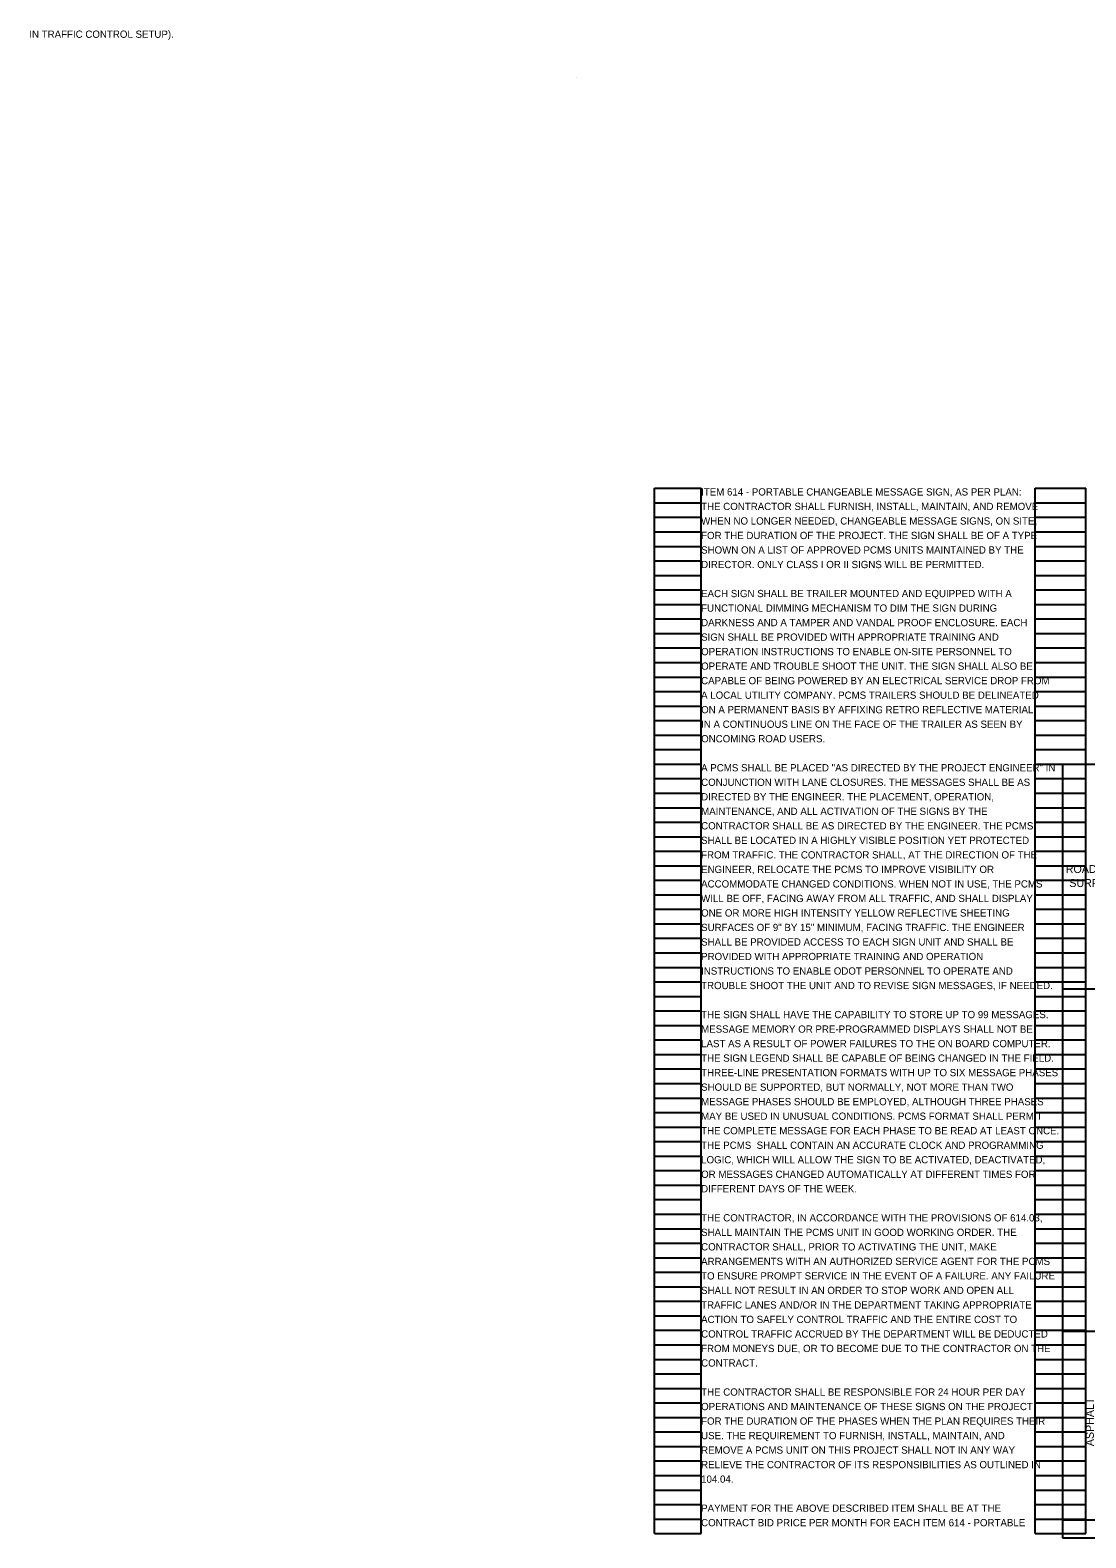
# Model space of a CAD drawing. Extents: x 0 to 37668, y -5 to 18949.
# Drawn here: x 37625.86 to 37646.22, y 18868.37 to 18897.45 of the extents above; entities that cross this region are included whole.
import ezdxf

# ---------------------------------------------------------------- set-up
doc = ezdxf.new("R2010")
doc.units = 0
doc.layers.add('SH_Data', color=7, linetype='Continuous')
doc.layers.add('SH_Text', color=7, linetype='Continuous')

msp = doc.modelspace()

# ---------------------------------------------------------------- linework, layer by layer
at = {"layer": 'SH_Data'}
for p, q in [((37636.401, 18896.542), (37636.401, 18896.542)), ((37637.901, 18868.45), (37637.901, 18888.61)), ((37637.901, 18888.61), (37638.801, 18888.61)), ((37638.801, 18868.45), (37638.801, 18888.61)), ((37645.241, 18868.45), (37645.241, 18888.61)), ((37645.241, 18888.61), (37646.221, 18888.61)), ((37646.221, 18868.45), (37646.221, 18888.61)), ((37637.901, 18888.33), (37638.801, 18888.33)), ((37645.241, 18888.33), (37646.221, 18888.33)), ((37637.901, 18888.05), (37638.801, 18888.05)), ((37645.241, 18888.05), (37646.221, 18888.05)), ((37637.901, 18887.77), (37638.801, 18887.77)), ((37645.241, 18887.77), (37646.221, 18887.77)), ((37637.901, 18887.49), (37638.801, 18887.49)), ((37645.241, 18887.49), (37646.221, 18887.49)), ((37637.901, 18887.21), (37638.801, 18887.21)), ((37637.901, 18886.93), (37638.801, 18886.93)), ((37645.241, 18887.21), (37646.221, 18887.21)), ((37645.241, 18886.93), (37646.221, 18886.93)), ((37637.901, 18886.65), (37638.801, 18886.65)), ((37645.241, 18886.65), (37646.221, 18886.65)), ((37637.901, 18886.37), (37638.801, 18886.37)), ((37645.241, 18886.37), (37646.221, 18886.37)), ((37637.901, 18886.09), (37638.801, 18886.09)), ((37645.241, 18886.09), (37646.221, 18886.09)), ((37637.901, 18885.81), (37638.801, 18885.81)), ((37645.241, 18885.81), (37646.221, 18885.81)), ((37637.901, 18885.53), (37638.801, 18885.53)), ((37645.241, 18885.53), (37646.221, 18885.53)), ((37637.901, 18885.25), (37638.801, 18885.25)), ((37645.241, 18885.25), (37646.221, 18885.25)), ((37637.901, 18884.97), (37638.801, 18884.97)), ((37645.241, 18884.97), (37646.221, 18884.97)), ((37637.901, 18884.69), (37638.801, 18884.69)), ((37645.241, 18884.69), (37646.221, 18884.69)), ((37637.901, 18884.41), (37638.801, 18884.41)), ((37645.241, 18884.41), (37646.221, 18884.41)), ((37637.901, 18884.13), (37638.801, 18884.13)), ((37645.241, 18884.13), (37646.221, 18884.13)), ((37637.901, 18883.85), (37638.801, 18883.85)), ((37645.241, 18883.85), (37646.221, 18883.85)), ((37637.901, 18883.57), (37638.801, 18883.57)), ((37645.241, 18883.57), (37646.221, 18883.57)), ((37637.901, 18883.29), (37638.801, 18883.29)), ((37645.241, 18883.29), (37646.221, 18883.29)), ((37637.901, 18883.01), (37638.801, 18883.01)), ((37645.241, 18883.01), (37646.221, 18883.01)), ((37637.901, 18882.73), (37638.801, 18882.73)), ((37645.241, 18882.73), (37646.221, 18882.73)), ((37637.901, 18882.45), (37638.801, 18882.45)), ((37645.241, 18882.45), (37646.221, 18882.45)), ((37637.901, 18882.17), (37638.801, 18882.17)), ((37645.241, 18882.17), (37646.221, 18882.17)), ((37637.901, 18881.89), (37638.801, 18881.89)), ((37645.241, 18881.89), (37646.221, 18881.89)), ((37637.901, 18881.61), (37638.801, 18881.61)), ((37645.241, 18881.61), (37646.221, 18881.61)), ((37637.901, 18881.33), (37638.801, 18881.33)), ((37645.241, 18881.33), (37646.221, 18881.33)), ((37637.901, 18881.05), (37638.801, 18881.05)), ((37645.241, 18881.05), (37646.221, 18881.05)), ((37637.901, 18880.77), (37638.801, 18880.77)), ((37645.241, 18880.77), (37646.221, 18880.77)), ((37637.901, 18880.49), (37638.801, 18880.49)), ((37645.241, 18880.49), (37646.221, 18880.49)), ((37637.901, 18880.21), (37638.801, 18880.21)), ((37645.241, 18880.21), (37646.221, 18880.21)), ((37637.901, 18879.93), (37638.801, 18879.93)), ((37645.241, 18879.93), (37646.221, 18879.93)), ((37637.901, 18879.65), (37638.801, 18879.65)), ((37637.901, 18879.37), (37638.801, 18879.37)), ((37645.241, 18879.65), (37646.221, 18879.65)), ((37645.241, 18879.37), (37646.221, 18879.37)), ((37637.901, 18879.09), (37638.801, 18879.09)), ((37645.241, 18879.09), (37646.221, 18879.09)), ((37637.901, 18878.81), (37638.801, 18878.81)), ((37645.241, 18878.81), (37646.221, 18878.81)), ((37637.901, 18878.53), (37638.801, 18878.53)), ((37645.241, 18878.53), (37646.221, 18878.53)), ((37637.901, 18878.25), (37638.801, 18878.25)), ((37645.241, 18878.25), (37646.221, 18878.25)), ((37637.901, 18877.97), (37638.801, 18877.97)), ((37645.241, 18877.97), (37646.221, 18877.97)), ((37637.901, 18877.69), (37638.801, 18877.69)), ((37645.241, 18877.69), (37646.221, 18877.69)), ((37637.901, 18877.41), (37638.801, 18877.41)), ((37645.241, 18877.41), (37646.221, 18877.41)), ((37637.901, 18877.13), (37638.801, 18877.13)), ((37645.241, 18877.13), (37646.221, 18877.13)), ((37637.901, 18876.85), (37638.801, 18876.85)), ((37645.241, 18876.85), (37646.221, 18876.85)), ((37637.901, 18876.57), (37638.801, 18876.57)), ((37645.241, 18876.57), (37646.221, 18876.57)), ((37637.901, 18876.29), (37638.801, 18876.29)), ((37645.241, 18876.29), (37646.221, 18876.29)), ((37637.901, 18876.01), (37638.801, 18876.01)), ((37645.241, 18876.01), (37646.221, 18876.01)), ((37637.901, 18875.73), (37638.801, 18875.73)), ((37645.241, 18875.73), (37646.221, 18875.73)), ((37637.901, 18875.45), (37638.801, 18875.45)), ((37645.241, 18875.45), (37646.221, 18875.45)), ((37637.901, 18875.17), (37638.801, 18875.17)), ((37645.241, 18875.17), (37646.221, 18875.17)), ((37637.901, 18874.89), (37638.801, 18874.89)), ((37645.241, 18874.89), (37646.221, 18874.89)), ((37637.901, 18874.61), (37638.801, 18874.61)), ((37645.241, 18874.61), (37646.221, 18874.61)), ((37637.901, 18874.33), (37638.801, 18874.33)), ((37645.241, 18874.33), (37646.221, 18874.33)), ((37637.901, 18874.05), (37638.801, 18874.05)), ((37645.241, 18874.05), (37646.221, 18874.05)), ((37637.901, 18873.77), (37638.801, 18873.77)), ((37645.241, 18873.77), (37646.221, 18873.77)), ((37637.901, 18873.49), (37638.801, 18873.49)), ((37645.241, 18873.49), (37646.221, 18873.49)), ((37637.901, 18873.21), (37638.801, 18873.21)), ((37645.241, 18873.21), (37646.221, 18873.21)), ((37637.901, 18872.93), (37638.801, 18872.93)), ((37645.241, 18872.93), (37646.221, 18872.93)), ((37637.901, 18872.65), (37638.801, 18872.65)), ((37645.241, 18872.65), (37646.221, 18872.65)), ((37637.901, 18872.37), (37638.801, 18872.37)), ((37645.241, 18872.37), (37646.221, 18872.37)), ((37637.901, 18872.09), (37638.801, 18872.09)), ((37637.901, 18871.81), (37638.801, 18871.81)), ((37645.241, 18872.09), (37646.221, 18872.09)), ((37645.241, 18871.81), (37646.221, 18871.81)), ((37637.901, 18871.53), (37638.801, 18871.53)), ((37645.241, 18871.53), (37646.221, 18871.53)), ((37637.901, 18871.25), (37638.801, 18871.25)), ((37645.241, 18871.25), (37646.221, 18871.25)), ((37637.901, 18870.97), (37638.801, 18870.97)), ((37645.241, 18870.97), (37646.221, 18870.97)), ((37637.901, 18870.69), (37638.801, 18870.69)), ((37645.241, 18870.69), (37646.221, 18870.69)), ((37637.901, 18870.41), (37638.801, 18870.41)), ((37645.241, 18870.41), (37646.221, 18870.41)), ((37637.901, 18870.13), (37638.801, 18870.13)), ((37645.241, 18870.13), (37646.221, 18870.13)), ((37637.901, 18869.85), (37638.801, 18869.85)), ((37645.241, 18869.85), (37646.221, 18869.85)), ((37637.901, 18869.57), (37638.801, 18869.57)), ((37645.241, 18869.57), (37646.221, 18869.57)), ((37637.901, 18869.29), (37638.801, 18869.29)), ((37645.241, 18869.29), (37646.221, 18869.29)), ((37637.901, 18869.01), (37638.801, 18869.01)), ((37645.241, 18869.01), (37646.221, 18869.01)), ((37637.901, 18868.73), (37638.801, 18868.73)), ((37645.241, 18868.73), (37646.221, 18868.73)), ((37637.901, 18868.45), (37638.801, 18868.45)), ((37645.241, 18868.45), (37646.221, 18868.45))]:
    msp.add_line(p, q, dxfattribs=at)
at = {"layer": 'SH_Text'}
for p, q in [((37645.771, 18883.29), (37658.947, 18883.29)), ((37645.771, 18883.29), (37645.771, 18868.367)), ((37645.771, 18878.958), (37658.947, 18878.958)), ((37645.771, 18872.353), (37658.947, 18872.353)), ((37645.771, 18868.713), (37658.947, 18868.713)), ((37645.771, 18868.367), (37658.947, 18868.367))]:
    msp.add_line(p, q, dxfattribs=at)

# ---------------------------------------------------------------- texts
for s, height, p in [('IN TRAFFIC CONTROL SETUP).', 0.14, (37625.844, 18897.298)), ('ITEM 614 - PORTABLE CHANGEABLE MESSAGE SIGN, AS PER PLAN:', 0.14, (37638.801, 18888.47)), ('THE CONTRACTOR SHALL FURNISH, INSTALL, MAINTAIN, AND REMOVE ', 0.14, (37638.801, 18888.19)), ('WHEN NO LONGER NEEDED, CHANGEABLE MESSAGE SIGNS, ON SITE, ', 0.14, (37638.801, 18887.91)), ('FOR THE DURATION OF THE PROJECT. THE SIGN SHALL BE OF A TYPE ', 0.14, (37638.801, 18887.63)), ('SHOWN ON A LIST OF APPROVED PCMS UNITS MAINTAINED BY THE ', 0.14, (37638.801, 18887.35)), ('DIRECTOR. ONLY CLASS I OR II SIGNS WILL BE PERMITTED.', 0.14, (37638.801, 18887.07)), ('EACH SIGN SHALL BE TRAILER MOUNTED AND EQUIPPED WITH A ', 0.14, (37638.801, 18886.51)), ('FUNCTIONAL DIMMING MECHANISM TO DIM THE SIGN DURING ', 0.14, (37638.801, 18886.23)), ('DARKNESS AND A TAMPER AND VANDAL PROOF ENCLOSURE. EACH ', 0.14, (37638.801, 18885.95)), ('SIGN SHALL BE PROVIDED WITH APPROPRIATE TRAINING AND ', 0.14, (37638.801, 18885.67)), ('OPERATION INSTRUCTIONS TO ENABLE ON-SITE PERSONNEL TO ', 0.14, (37638.801, 18885.39)), ('OPERATE AND TROUBLE SHOOT THE UNIT. THE SIGN SHALL ALSO BE ', 0.14, (37638.801, 18885.11)), ('CAPABLE OF BEING POWERED BY AN ELECTRICAL SERVICE DROP FROM ', 0.14, (37638.801, 18884.83)), ('A LOCAL UTILITY COMPANY. PCMS TRAILERS SHOULD BE DELINEATED ', 0.14, (37638.801, 18884.55)), ('ON A PERMANENT BASIS BY AFFIXING RETRO REFLECTIVE MATERIAL, ', 0.14, (37638.801, 18884.27)), ('IN A CONTINUOUS LINE ON THE FACE OF THE TRAILER AS SEEN BY ', 0.14, (37638.801, 18883.99)), ('ONCOMING ROAD USERS.', 0.14, (37638.801, 18883.71)), ('A PCMS SHALL BE PLACED "AS DIRECTED BY THE PROJECT ENGINEER" IN ', 0.14, (37638.801, 18883.15)), ('CONJUNCTION WITH LANE CLOSURES. THE MESSAGES SHALL BE AS ', 0.14, (37638.801, 18882.87)), ('DIRECTED BY THE ENGINEER. THE PLACEMENT, OPERATION, ', 0.14, (37638.801, 18882.59)), ('MAINTENANCE, AND ALL ACTIVATION OF THE SIGNS BY THE ', 0.14, (37638.801, 18882.31)), ('CONTRACTOR SHALL BE AS DIRECTED BY THE ENGINEER. THE PCMS ', 0.14, (37638.801, 18882.03)), ('SHALL BE LOCATED IN A HIGHLY VISIBLE POSITION YET PROTECTED ', 0.14, (37638.801, 18881.75)), ('FROM TRAFFIC. THE CONTRACTOR SHALL, AT THE DIRECTION OF THE ', 0.14, (37638.801, 18881.47)), ('ENGINEER, RELOCATE THE PCMS TO IMPROVE VISIBILITY OR ', 0.14, (37638.801, 18881.19)), ('ROADWAY ', 0.154, (37645.834, 18881.19)), ('ACCOMMODATE CHANGED CONDITIONS. WHEN NOT IN USE, THE PCMS ', 0.14, (37638.801, 18880.91)), ('SURFACE', 0.154, (37645.902, 18880.92)), ('WILL BE OFF, FACING AWAY FROM ALL TRAFFIC, AND SHALL DISPLAY ', 0.14, (37638.801, 18880.63)), ('ONE OR MORE HIGH INTENSITY YELLOW REFLECTIVE SHEETING ', 0.14, (37638.801, 18880.35)), ('SURFACES OF 9" BY 15" MINIMUM, FACING TRAFFIC. THE ENGINEER ', 0.14, (37638.801, 18880.07)), ('SHALL BE PROVIDED ACCESS TO EACH SIGN UNIT AND SHALL BE ', 0.14, (37638.801, 18879.79)), ('PROVIDED WITH APPROPRIATE TRAINING AND OPERATION ', 0.14, (37638.801, 18879.51)), ('INSTRUCTIONS TO ENABLE ODOT PERSONNEL TO OPERATE AND ', 0.14, (37638.801, 18879.23)), ('TROUBLE SHOOT THE UNIT AND TO REVISE SIGN MESSAGES, IF NEEDED.', 0.14, (37638.801, 18878.95)), ('THE SIGN SHALL HAVE THE CAPABILITY TO STORE UP TO 99 MESSAGES. ', 0.14, (37638.801, 18878.39)), ('MESSAGE MEMORY OR PRE-PROGRAMMED DISPLAYS SHALL NOT BE ', 0.14, (37638.801, 18878.11)), ('LAST AS A RESULT OF POWER FAILURES TO THE ON BOARD COMPUTER. ', 0.14, (37638.801, 18877.83)), ('THE SIGN LEGEND SHALL BE CAPABLE OF BEING CHANGED IN THE FIELD. ', 0.14, (37638.801, 18877.55)), ('THREE-LINE PRESENTATION FORMATS WITH UP TO SIX MESSAGE PHASES ', 0.14, (37638.801, 18877.27)), ('SHOULD BE SUPPORTED, BUT NORMALLY, NOT MORE THAN TWO ', 0.14, (37638.801, 18876.99)), ('MESSAGE PHASES SHOULD BE EMPLOYED, ALTHOUGH THREE PHASES ', 0.14, (37638.801, 18876.71)), ('MAY BE USED IN UNUSUAL CONDITIONS. PCMS FORMAT SHALL PERMIT ', 0.14, (37638.801, 18876.43)), ('THE COMPLETE MESSAGE FOR EACH PHASE TO BE READ AT LEAST ONCE. ', 0.14, (37638.801, 18876.15)), ('THE PCMS  SHALL CONTAIN AN ACCURATE CLOCK AND PROGRAMMING ', 0.14, (37638.801, 18875.87)), ('LOGIC, WHICH WILL ALLOW THE SIGN TO BE ACTIVATED, DEACTIVATED, ', 0.14, (37638.801, 18875.59)), ('OR MESSAGES CHANGED AUTOMATICALLY AT DIFFERENT TIMES FOR ', 0.14, (37638.801, 18875.31)), ('DIFFERENT DAYS OF THE WEEK.', 0.14, (37638.801, 18875.03)), ('THE CONTRACTOR, IN ACCORDANCE WITH THE PROVISIONS OF 614.03, ', 0.14, (37638.801, 18874.47)), ('SHALL MAINTAIN THE PCMS UNIT IN GOOD WORKING ORDER. THE ', 0.14, (37638.801, 18874.19)), ('CONTRACTOR SHALL, PRIOR TO ACTIVATING THE UNIT, MAKE ', 0.14, (37638.801, 18873.91)), ('ARRANGEMENTS WITH AN AUTHORIZED SERVICE AGENT FOR THE PCMS ', 0.14, (37638.801, 18873.63)), ('TO ENSURE PROMPT SERVICE IN THE EVENT OF A FAILURE. ANY FAILURE ', 0.14, (37638.801, 18873.35)), ('SHALL NOT RESULT IN AN ORDER TO STOP WORK AND OPEN ALL ', 0.14, (37638.801, 18873.07)), ('TRAFFIC LANES AND/OR IN THE DEPARTMENT TAKING APPROPRIATE ', 0.14, (37638.801, 18872.79)), ('ACTION TO SAFELY CONTROL TRAFFIC AND THE ENTIRE COST TO ', 0.14, (37638.801, 18872.51)), ('CONTROL TRAFFIC ACCRUED BY THE DEPARTMENT WILL BE DEDUCTED ', 0.14, (37638.801, 18872.23)), ('CONTRACT.', 0.14, (37638.801, 18871.67)), ('FROM MONEYS DUE, OR TO BECOME DUE TO THE CONTRACTOR ON THE ', 0.14, (37638.801, 18871.95)), ('THE CONTRACTOR SHALL BE RESPONSIBLE FOR 24 HOUR PER DAY ', 0.14, (37638.801, 18871.11)), ('OPERATIONS AND MAINTENANCE OF THESE SIGNS ON THE PROJECT ', 0.14, (37638.801, 18870.83)), ('FOR THE DURATION OF THE PHASES WHEN THE PLAN REQUIRES THEIR ', 0.14, (37638.801, 18870.55)), ('USE. THE REQUIREMENT TO FURNISH, INSTALL, MAINTAIN, AND ', 0.14, (37638.801, 18870.27)), ('REMOVE A PCMS UNIT ON THIS PROJECT SHALL NOT IN ANY WAY ', 0.14, (37638.801, 18869.99)), ('RELIEVE THE CONTRACTOR OF ITS RESPONSIBILITIES AS OUTLINED IN ', 0.14, (37638.801, 18869.71)), ('104.04.', 0.14, (37638.801, 18869.43)), ('PAYMENT FOR THE ABOVE DESCRIBED ITEM SHALL BE AT THE ', 0.14, (37638.801, 18868.87)), ('CONTRACT BID PRICE PER MONTH FOR EACH ITEM 614 - PORTABLE ', 0.14, (37638.801, 18868.59))]:
    msp.add_text(s, height=height, dxfattribs=at).set_placement(p)
msp.add_text('ASPHALT', height=0.154, rotation=90, dxfattribs=at).set_placement((37646.375, 18870.135))

doc.saveas('drawing.dxf')
